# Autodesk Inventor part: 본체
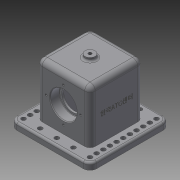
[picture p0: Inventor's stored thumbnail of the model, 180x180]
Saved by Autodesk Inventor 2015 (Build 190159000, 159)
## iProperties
Created: 2018-11
Part Number: 본체
Material: 일반
Document SubType Name: Modeling
Designer: now
Density: 1 g/cm^3
Appearance: 기본값
Mass: 376.063 g
Surface Area: 780.986 cm^2
Volume: 376.063 cm^3
Author: now
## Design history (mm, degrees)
sketch "스케치1"
  geometry: L1 (-60, 60)-(60, 60); L2 (60, 60)-(60, -60); L3 (60, -60)-(-60, -60); L4 (-60, -60)-(-60, 60); L5 (-60, 60)-(60, -60); L6 (60, 60)-(-60, -60); 1 further point
  constraints: 12 end point, 2 midpoint, 2 parallel, 1 horizontal, 1 perpendicular
  dimensions: "d0" = 120 distance of L3.end L1.start; "d1" = 120 distance of L1.start L1.end
extrude "돌출1" new body sketch "스케치1" distance "d2" = 10; taper "d3" = 0 deg
sketch "스케치2"
  geometry: L1 (-40, 40)-(40, 40); L2 (40, 40)-(40, -40); L3 (40, -40)-(-40, -40); L4 (-40, -40)-(-40, 40); L5 (-40, 40)-(40, -40); L6 (40, 40)-(-40, -40); 1 further point
  constraints: 12 end point, 2 midpoint, 2 parallel, 1 horizontal, 1 perpendicular
  dimensions: "d4" = 80 distance of L2.end L3.end; "d5" = 80 distance of L1.end L2.end
extrude "돌출2" join sketch "스케치2" distance "d6" = 80; taper "d7" = 0 deg
sketch "스케치3"
  geometry: L1 (30, 23)-(-30, 23); L2 (-30, 23)-(-30, -23); L3 (-30, -23)-(30, -23); L4 (30, -23)-(30, 23); L5 (30, 23)-(-30, -23); L6 (-30, 23)-(30, -23); 1 further point
  constraints: 12 end point, 2 midpoint, 2 parallel, 1 horizontal, 1 perpendicular
  dimensions: "d8" = 60 distance of L2.end L3.end; "d9" = 46 distance of L1.end L2.end
extrude "돌출3" cut sketch "스케치3" distance "d10" = 80; taper "d11" = 0 deg
sketch "스케치4"
  geometry: L1 (-20, -10)-(-20, 0) reference; L2 (-20, 0)-(0, 0) reference; L3 (0, 0)-(0, 80) reference; L4 (0, 80)-(80, 80) reference; L5 (80, 80)-(80, 0) reference; L6 (80, 0)-(100, 0) reference; L7 (100, 0)-(100, -10) reference; L8 (100, -10)-(-20, -10) reference; L9 (0, 0)-(80, 0) reference; C1 r 16.5 at (40, 38); 2 further points
  constraints: 1 centre point, 1 midpoint, 1 vertical alignment
  dimensions: "d12" = 33 diameter of C1; "d13" = 48 distance of point (40, -10) C1.centre
extrude "돌출4" cut sketch "스케치4" stored distance "d14" = 80; taper "d15" = 0 deg
sketch "스케치5"
  geometry: C1 r 16.5 at (40, 38) reference; C2 r 20 at (40, 38); 1 further point
  constraints: 1 centre point, 1 coincident
  dimensions: "d16" = 40 diameter of C2
extrude "돌출5" cut sketch "스케치5" distance "d17" = 14; taper "d18" = 0 deg
fillet "모깎기1" dims "d19" = 0.6
node "작업 평면1"
sketch "스케치6"
  geometry: C1 r 7.5 at (0, 0); 1 further point
  constraints: 1 centre point, 1 coincident
  dimensions: "d21" = 15 diameter of C1
extrude "돌출6" join sketch "스케치6" stored distance "d22" = 14; taper "d23" = 0 deg
sketch "스케치7"
  geometry: C1 r 7.5 at (0, 0) reference
hole "구멍1" sketch "스케치7" at (0, 0) diameter "d24" = 4.917; stored, may be unused: countersink angle "d28" = 90 deg, drill point angle "d30" = 0 deg; dims "d25" = 15, "d26" = 4, "d27" = 2, "d29" = 16
sketch "스케치8" dims "d31" = 52
  geometry: C1 r 20 at (40, 38) reference; 3 further points
  constraints: 2 vertical alignment, 1 coincident, 2 other
hole "구멍2" sketch "스케치8" at (40, 64) diameter "d32" = 3.242; stored, may be unused: countersink angle "d36" = 90 deg, drill point angle "d38" = 118 deg; dims "d33" = 8, "d34" = 4, "d35" = 2, "d37" = 10
fillet "모깎기2" dims "d42" = 10
sketch "스케치9"
  geometry: L1 (-60, -50)-(-60, 50) reference; L2 (-50, 60)-(50, 60) reference; L3 (60, 50)-(60, -50) reference; L4 (50, -60)-(-50, -60) reference; L5 (30, -23)-(30, 23) reference; L6 (30, 23)-(-30, 23) reference; L7 (-30, 23)-(-30, -23) reference; L8 (-30, -23)-(30, -23) reference; L9 (40, 40)-(40, -40) reference; L10 (40, -40)-(-40, -40) reference; L11 (-40, -40)-(-40, 40) reference; L12 (-40, 40)-(40, 40) reference; A1 r 10 centre (-50, -50) between (-60, -50) and (-50, -60) reference; A2 r 10 centre (-50, -50) between (-60, -50) and (-50, -60) reference; A3 r 10 centre (-50, 50) between (-50, 60) and (-60, 50) reference; A4 r 10 centre (50, 50) between (60, 50) and (50, 60) reference; A5 r 10 centre (50, -50) between (50, -60) and (60, -50) reference; 1 further point
hole "구멍3" sketch "스케치9" at (-50, -50) diameter "d43" = 6.6; stored, may be unused: countersink angle "d47" = 90 deg, drill point angle "d49" = 118 deg; dims "d44" = 8, "d45" = 4, "d46" = 2, "d48" = 10
fillet "모깎기3" dims "d62" = 8
fillet "모깎기4" dims "d63" = 8
fillet "모깎기5" dims "d64" = 3
fillet "모깎기6" dims "d65" = 3
chamfer "모따기1" distance "d66" = 1; stored, may be unused: second distance "d67" = 2, angle "d68" = 45 deg
chamfer "모따기2" distance "d69" = 1; stored, may be unused: second distance "d70" = 2, angle "d71" = 45 deg
sketch "스케치10"
  geometry: L1 (10, 82)-(10, -18) reference; L2 (-72, -8)-(0, -8) reference; 2 further points
  constraints: 1 other
  dimensions: "d72" = 48 distance from line of L1 point (-38, 32); "d73" = 40 distance from line of L2 point (-38, 32)
feature "엠보싱1" sketch "스케치10" dims "d0" = 120, "d1" = 120, "d8" = 60, "d9" = 46, "d74" = 0.5, "d75" = 0
node "솔리드1"
mirror "대칭1"
pattern_circular "원형 패턴1" dims angle "d40" = 360 deg
mirror "대칭2"
pattern_linear "직사각형 패턴1" dims "d52" = 10
pattern_linear "직사각형 패턴2" dims "d58" = 25
node "절단 모서리 투영1"
node "절단 모서리 투영2"
other parameters: "d20" = 95
